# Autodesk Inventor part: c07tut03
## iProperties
Shininess: 77.0
Length Units: 11269
Angle Units: 11279
Time Units: 11290
Mass Units: 11283
Length Display Precision: 3
Angle Display Precision: 2
Created: 2002-01
Part Number: c07tut03
Document SubType Name: Modeling
Designer: ***
Density: 0.0
Volumn: 0.0
Area: 0.0
PropertySet Name: Model Information
Control State: 0
Master: False
Checked Out: False
Author: ***
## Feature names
1. Extrusion1
2. Fillet1
3. Extrusion2
